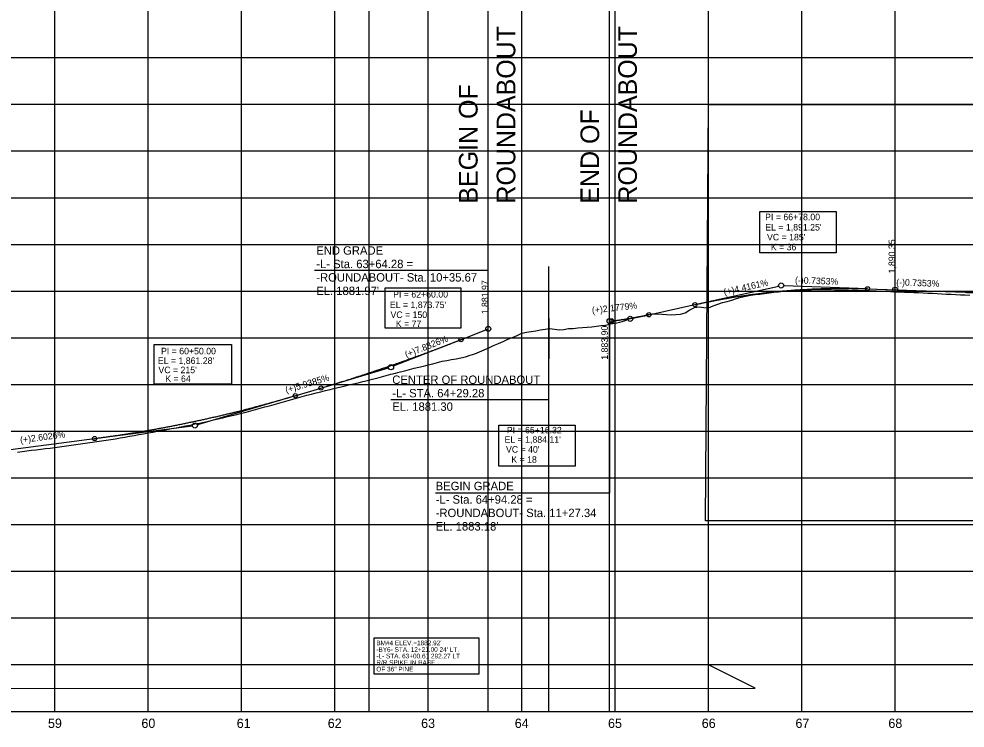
# Model space of a CAD drawing. Extents: x 553912 to 567693, y 512355 to 537539.
# Drawn here: x 562111 to 563124, y 513588 to 514347 of the extents above; entities that cross this region are included whole.
import ezdxf

# ---------------------------------------------------------------- set-up
doc = ezdxf.new("R2010")
doc.units = 0
for name, color, linetype in [('Exist DTM Spot Elevation Text', 7, 'Continuous'), ('Exist Profile Cell', 7, 'Continuous'), ('Exist Vertical Profile Ground Line', 7, 'Continuous'), ('Exist Vertical Profile Horizontal Axis Label Major', 7, 'Continuous'), ('Prop Vertical Profile Curve Label', 7, 'Continuous'), ('Prop Vertical Profile Grade', 7, 'Continuous'), ('Prop Vertical Profile Grade Label', 7, 'Continuous'), ('Prop VPI Label', 7, 'Continuous'), ('Scratch_Level_1', 7, 'Continuous'), ('Scratch_Level_5', 7, 'Continuous'), ('Sheet Profile Grid Major CELL', 7, 'Continuous')]:
    doc.layers.add(name, color=color, linetype=linetype)

msp = doc.modelspace()

# ---------------------------------------------------------------- linework, layer by layer
at = {"layer": 'Exist DTM Spot Elevation Text'}
msp.add_lwpolyline([(562491.3, 513645.9), (562603.8, 513645.9), (562603.8, 513683.9), (562491.3, 513683.9)], close=True, dxfattribs=at)
at = {"layer": 'Exist Profile Cell'}
msp.add_line((557249.5, 513605.4), (563849.5, 513605.4), dxfattribs=at)
msp.add_line((557249.5, 513605.4), (563849.5, 513605.4), dxfattribs=at)
at = {"layer": 'Exist Vertical Profile Ground Line'}
for points in [[(562749.5, 514021.5), (562754.5, 514022.4), (562759.5, 514024), (562764.5, 514026.1), (562769.5, 514027.4), (562774.5, 514028.4), (562779.5, 514029.4), (562784.5, 514030.5), (562789.5, 514031.5), (562794.5, 514031.2), (562799.5, 514030.9), (562804.5, 514030.6), (562809.5, 514030.4), (562814.5, 514030.6), (562819.5, 514030.9), (562824.5, 514032.3), (562829.5, 514035.7), (562834.5, 514038.2), (562839.5, 514039), (562844.5, 514038.3), (562849.5, 514037.9), (562854.5, 514040), (562859.5, 514041.8), (562864.5, 514043.4), (562869.5, 514044.7), (562874.5, 514046.1), (562879.5, 514047.8), (562884.5, 514049.3), (562889.5, 514050.3), (562894.5, 514051.2), (562899.5, 514051.9), (562904.5, 514052.6), (562909.5, 514053.3), (562914.5, 514053.9), (562919.5, 514054.5), (562924.5, 514055.1), (562929.5, 514055.7), (562934.5, 514056.2), (562939.5, 514056.4), (562944.5, 514056.6), (562949.5, 514056.8), (562954.5, 514057), (562959.5, 514057.2), (562964.5, 514057.4), (562969.5, 514057.5), (562974.5, 514057.4), (562979.5, 514057.3), (562984.5, 514057.2), (562989.5, 514057.1), (562994.5, 514057), (562999.5, 514056.9), (563004.5, 514056.8), (563009.5, 514056.6), (563014.5, 514056.4), (563019.5, 514056.3), (563024.5, 514056.1), (563029.5, 514055.9), (563034.5, 514055.7), (563039.5, 514055.5), (563044.5, 514055.3), (563049.5, 514055.1), (563054.5, 514054.9), (563059.5, 514054.7), (563064.5, 514054.5), (563069.5, 514054.3), (563074.5, 514054.1), (563079.5, 514053.9), (563084.5, 514053.6), (563089.5, 514053.4), (563094.5, 514053.1), (563099.5, 514052.9), (563104.5, 514052.6), (563109.5, 514052.3), (563114.5, 514052.1), (563119.5, 514051.8), (563124.5, 514051.6), (563129.5, 514051.3)], [(562749.5, 514021.5), (562754.5, 514022.4), (562759.5, 514024), (562764.5, 514026.1), (562769.5, 514027.4), (562774.5, 514028.4), (562779.5, 514029.4), (562784.5, 514030.5), (562789.5, 514031.5), (562794.5, 514031.2), (562799.5, 514030.9), (562804.5, 514030.6), (562809.5, 514030.4), (562814.5, 514030.6), (562819.5, 514030.9), (562824.5, 514032.3), (562829.5, 514035.7), (562834.5, 514038.2), (562839.5, 514039), (562844.5, 514038.3), (562849.5, 514037.9), (562854.5, 514040), (562859.5, 514041.8), (562864.5, 514043.4), (562869.5, 514044.7), (562874.5, 514046.1), (562879.5, 514047.8), (562884.5, 514049.3), (562889.5, 514050.3), (562894.5, 514051.2), (562899.5, 514051.9), (562904.5, 514052.6), (562909.5, 514053.3), (562914.5, 514053.9), (562919.5, 514054.5), (562924.5, 514055.1), (562929.5, 514055.7), (562934.5, 514056.2), (562939.5, 514056.4), (562944.5, 514056.6), (562949.5, 514056.8), (562954.5, 514057), (562959.5, 514057.2), (562964.5, 514057.4), (562969.5, 514057.5), (562974.5, 514057.4), (562979.5, 514057.3), (562984.5, 514057.2), (562989.5, 514057.1), (562994.5, 514057), (562999.5, 514056.9), (563004.5, 514056.8), (563009.5, 514056.6), (563014.5, 514056.4), (563019.5, 514056.3), (563024.5, 514056.1), (563029.5, 514055.9), (563034.5, 514055.7), (563039.5, 514055.5), (563044.5, 514055.3), (563049.5, 514055.1), (563054.5, 514054.9), (563059.5, 514054.7), (563064.5, 514054.5), (563069.5, 514054.3), (563074.5, 514054.1), (563079.5, 514053.9), (563084.5, 514053.6), (563089.5, 514053.4), (563094.5, 514053.1), (563099.5, 514052.9), (563104.5, 514052.6), (563109.5, 514052.3), (563114.5, 514052.1), (563119.5, 514051.8), (563124.5, 514051.6), (563129.5, 514051.3)], [(562249.5, 513903.9), (562254.5, 513904.8), (562259.5, 513905.7), (562264.5, 513906.6), (562269.5, 513907.6), (562274.5, 513908.5), (562279.5, 513909.4), (562284.5, 513910.4), (562289.5, 513911.3), (562294.5, 513912.3), (562299.5, 513913.4), (562304.5, 513914.4), (562309.5, 513915.5), (562314.5, 513916.6), (562319.5, 513917.8), (562324.5, 513919), (562329.5, 513920.1), (562334.5, 513921.3), (562339.5, 513922.5), (562344.5, 513923.7), (562349.5, 513925), (562354.5, 513926.2), (562359.5, 513927.6), (562364.5, 513928.9), (562369.5, 513930.3), (562374.5, 513931.6), (562379.5, 513933), (562384.5, 513934.4), (562389.5, 513935.8), (562394.5, 513937.2), (562399.5, 513938.6), (562404.5, 513940), (562409.5, 513941.4), (562414.5, 513942.8), (562419.5, 513944.1), (562424.5, 513945.5), (562429.5, 513946.8), (562434.5, 513948), (562439.5, 513949.2), (562444.5, 513950.4), (562449.5, 513951.6), (562454.5, 513952.8), (562459.5, 513953.9), (562464.5, 513955.2), (562469.5, 513956.4), (562474.5, 513957.6), (562479.5, 513958.9), (562484.5, 513960.1), (562489.5, 513961.3), (562494.5, 513962.6), (562499.5, 513963.9), (562504.5, 513965.2), (562509.5, 513966.6), (562514.5, 513967.9), (562519.5, 513969.2), (562524.5, 513970.5), (562529.5, 513971.8), (562534.5, 513973.1), (562539.5, 513974.3), (562544.5, 513975.5), (562549.5, 513976.7), (562554.5, 513978), (562559.5, 513979.2), (562564.5, 513980.5), (562569.5, 513981.5), (562574.5, 513982.4), (562579.5, 513983.3), (562584.5, 513984.1), (562589.5, 513985.2), (562594.5, 513987), (562599.5, 513988.6), (562604.5, 513990.7), (562609.5, 513992.8), (562614.5, 513995), (562619.5, 513997.3), (562624.5, 513999.6), (562629.5, 514001.9), (562634.5, 514004.1), (562639.5, 514006.2), (562644.5, 514008.3), (562649.5, 514010.6), (562654.5, 514011.8), (562659.5, 514012.4), (562664.5, 514013.3), (562669.5, 514014.2), (562674.5, 514015.1), (562679.5, 514015.8), (562684.5, 514015), (562689.5, 514014.4), (562694.5, 514014.5), (562699.5, 514015.7), (562704.5, 514015.8), (562709.5, 514016.2), (562714.5, 514016.7), (562719.5, 514017.1), (562724.5, 514017.6), (562729.5, 514018.2), (562734.5, 514018.8), (562739.5, 514019.2), (562744.5, 514020.5), (562749.5, 514021.5)], [(562249.5, 513903.9), (562254.5, 513904.8), (562259.5, 513905.7), (562264.5, 513906.6), (562269.5, 513907.6), (562274.5, 513908.5), (562279.5, 513909.4), (562284.5, 513910.4), (562289.5, 513911.3), (562294.5, 513912.3), (562299.5, 513913.4), (562304.5, 513914.4), (562309.5, 513915.5), (562314.5, 513916.6), (562319.5, 513917.8), (562324.5, 513919), (562329.5, 513920.1), (562334.5, 513921.3), (562339.5, 513922.5), (562344.5, 513923.7), (562349.5, 513925), (562354.5, 513926.2), (562359.5, 513927.6), (562364.5, 513928.9), (562369.5, 513930.3), (562374.5, 513931.6), (562379.5, 513933), (562384.5, 513934.4), (562389.5, 513935.8), (562394.5, 513937.2), (562399.5, 513938.6), (562404.5, 513940), (562409.5, 513941.4), (562414.5, 513942.8), (562419.5, 513944.1), (562424.5, 513945.5), (562429.5, 513946.8), (562434.5, 513948), (562439.5, 513949.2), (562444.5, 513950.4), (562449.5, 513951.6), (562454.5, 513952.8), (562459.5, 513953.9), (562464.5, 513955.2), (562469.5, 513956.4), (562474.5, 513957.6), (562479.5, 513958.9), (562484.5, 513960.1), (562489.5, 513961.3), (562494.5, 513962.6), (562499.5, 513963.9), (562504.5, 513965.2), (562509.5, 513966.6), (562514.5, 513967.9), (562519.5, 513969.2), (562524.5, 513970.5), (562529.5, 513971.8), (562534.5, 513973.1), (562539.5, 513974.3), (562544.5, 513975.5), (562549.5, 513976.7), (562554.5, 513978), (562559.5, 513979.2), (562564.5, 513980.5), (562569.5, 513981.5), (562574.5, 513982.4), (562579.5, 513983.3), (562584.5, 513984.1), (562589.5, 513985.2), (562594.5, 513987), (562599.5, 513988.6), (562604.5, 513990.7), (562609.5, 513992.8), (562614.5, 513995), (562619.5, 513997.3), (562624.5, 513999.6), (562629.5, 514001.9), (562634.5, 514004.1), (562639.5, 514006.2), (562644.5, 514008.3), (562649.5, 514010.6), (562654.5, 514011.8), (562659.5, 514012.4), (562664.5, 514013.3), (562669.5, 514014.2), (562674.5, 514015.1), (562679.5, 514015.8), (562684.5, 514015), (562689.5, 514014.4), (562694.5, 514014.5), (562699.5, 514015.7), (562704.5, 514015.8), (562709.5, 514016.2), (562714.5, 514016.7), (562719.5, 514017.1), (562724.5, 514017.6), (562729.5, 514018.2), (562734.5, 514018.8), (562739.5, 514019.2), (562744.5, 514020.5), (562749.5, 514021.5)], [(562109.5, 513883.4), (562114.5, 513884), (562119.5, 513884.6), (562124.5, 513885.2), (562129.5, 513885.8), (562134.5, 513886.4), (562139.5, 513887), (562144.5, 513887.6), (562149.5, 513888.3), (562154.5, 513888.9), (562159.5, 513889.6), (562164.5, 513890.3), (562169.5, 513891), (562174.5, 513891.7), (562179.5, 513892.4), (562184.5, 513893.1), (562189.5, 513893.9), (562194.5, 513894.6), (562199.5, 513895.3), (562204.5, 513896), (562209.5, 513896.8), (562214.5, 513897.6), (562219.5, 513898.4), (562224.5, 513899.3), (562229.5, 513900.2), (562234.5, 513901.1), (562239.5, 513902), (562244.5, 513902.9), (562249.5, 513903.9)], [(562109.5, 513883.4), (562114.5, 513884), (562119.5, 513884.6), (562124.5, 513885.2), (562129.5, 513885.8), (562134.5, 513886.4), (562139.5, 513887), (562144.5, 513887.6), (562149.5, 513888.3), (562154.5, 513888.9), (562159.5, 513889.6), (562164.5, 513890.3), (562169.5, 513891), (562174.5, 513891.7), (562179.5, 513892.4), (562184.5, 513893.1), (562189.5, 513893.9), (562194.5, 513894.6), (562199.5, 513895.3), (562204.5, 513896), (562209.5, 513896.8), (562214.5, 513897.6), (562219.5, 513898.4), (562224.5, 513899.3), (562229.5, 513900.2), (562234.5, 513901.1), (562239.5, 513902), (562244.5, 513902.9), (562249.5, 513903.9)]]:
    msp.add_lwpolyline(points, dxfattribs=at)
at = {"layer": 'Prop Vertical Profile Curve Label'}
for centre in [(563020, 514058.2), (562835, 514041.2), (562745.8, 514023.8), (562785.8, 514030.4), (562584.5, 514003.7), (562407, 513943.7), (562434.5, 513951.9), (562192, 513897.8)]:
    msp.add_circle(centre, 2.25, dxfattribs=at)
at = {"layer": 'Prop Vertical Profile Grade'}
for p, q in [((563020, 514058.2), (563124.5, 514054.4)), ((563020, 514058.2), (563049.5, 514057.2)), ((562785.8, 514030.4), (562835, 514041.2)), ((562743.7, 514023.6), (562745.8, 514023.8)), ((562584.5, 514003.7), (562613.7, 514015.3)), ((562407, 513943.7), (562434.5, 513951.9)), ((562049.5, 513879.3), (562192, 513897.8))]:
    msp.add_line(p, q, dxfattribs=at)
for points in [[(562835, 514041.2), (562838.7, 514042), (562842.4, 514042.8), (562846.1, 514043.6), (562849.8, 514044.3), (562853.5, 514045.1), (562857.2, 514045.8), (562860.9, 514046.5), (562864.6, 514047.2), (562868.3, 514047.8), (562872, 514048.4), (562875.7, 514049.1), (562879.4, 514049.7), (562883.1, 514050.2), (562886.8, 514050.8), (562890.5, 514051.3), (562894.2, 514051.9), (562897.9, 514052.4), (562901.6, 514052.8), (562905.3, 514053.3), (562909, 514053.8), (562912.7, 514054.2), (562916.4, 514054.6), (562920.1, 514055), (562923.8, 514055.3), (562927.5, 514055.7), (562931.2, 514056), (562934.9, 514056.3), (562938.6, 514056.6), (562942.3, 514056.9), (562946, 514057.2), (562949.7, 514057.4), (562953.4, 514057.6), (562957.1, 514057.8), (562960.8, 514058), (562964.5, 514058.1), (562968.2, 514058.3), (562971.9, 514058.4), (562975.6, 514058.5), (562979.3, 514058.6), (562983, 514058.7), (562986.7, 514058.7), (562990.4, 514058.7), (562994.1, 514058.7), (562997.8, 514058.7), (563001.5, 514058.7), (563005.2, 514058.6), (563008.9, 514058.6), (563012.6, 514058.5), (563016.3, 514058.4), (563020, 514058.2)], [(563124.5, 514054.4), (563127.5, 514054.3), (563130.5, 514054.2), (563133.5, 514054.1), (563136.5, 514053.9), (563139.5, 514053.8), (563142.5, 514053.7), (563145.5, 514053.6), (563148.5, 514053.4), (563151.5, 514053.3), (563154.5, 514053.2), (563157.5, 514053), (563160.5, 514052.9), (563163.5, 514052.8), (563166.5, 514052.6), (563169.5, 514052.5), (563172.5, 514052.3), (563175.5, 514052.2), (563178.5, 514052), (563181.5, 514051.9), (563184.5, 514051.7), (563187.5, 514051.5), (563190.5, 514051.4), (563193.5, 514051.2), (563196.5, 514051), (563199.5, 514050.9), (563202.5, 514050.7), (563205.5, 514050.5), (563208.5, 514050.3), (563211.5, 514050.2), (563214.5, 514050), (563217.5, 514049.8), (563220.5, 514049.6), (563223.5, 514049.4), (563226.5, 514049.2), (563229.5, 514049), (563232.5, 514048.8), (563235.5, 514048.6), (563238.5, 514048.4), (563241.5, 514048.2), (563244.5, 514048), (563247.5, 514047.8), (563250.5, 514047.6), (563253.5, 514047.3), (563256.5, 514047.1), (563259.5, 514046.9), (563262.5, 514046.7), (563265.5, 514046.5), (563268.5, 514046.2), (563271.5, 514046), (563274.5, 514045.8)], [(562745.8, 514023.8), (562746.6, 514023.9), (562747.4, 514024), (562748.2, 514024), (562749, 514024.1), (562749.8, 514024.2), (562750.6, 514024.3), (562751.4, 514024.4), (562752.2, 514024.5), (562753, 514024.6), (562753.8, 514024.7), (562754.6, 514024.8), (562755.4, 514024.9), (562756.2, 514025.1), (562757, 514025.2), (562757.8, 514025.3), (562758.6, 514025.4), (562759.4, 514025.5), (562760.2, 514025.6), (562761, 514025.8), (562761.8, 514025.9), (562762.6, 514026), (562763.4, 514026.1), (562764.2, 514026.2), (562765, 514026.4), (562765.8, 514026.5), (562766.6, 514026.6), (562767.4, 514026.8), (562768.2, 514026.9), (562769, 514027.1), (562769.8, 514027.2), (562770.6, 514027.3), (562771.4, 514027.5), (562772.2, 514027.6), (562773, 514027.8), (562773.8, 514027.9), (562774.6, 514028.1), (562775.4, 514028.2), (562776.2, 514028.4), (562777, 514028.5), (562777.8, 514028.7), (562778.6, 514028.8), (562779.4, 514029), (562780.2, 514029.2), (562781, 514029.3), (562781.8, 514029.5), (562782.6, 514029.7), (562783.4, 514029.8), (562784.2, 514030), (562785, 514030.2), (562785.8, 514030.4)], [(562434.5, 513951.9), (562437.5, 513952.8), (562440.5, 513953.7), (562443.5, 513954.6), (562446.5, 513955.5), (562449.5, 513956.4), (562452.5, 513957.3), (562455.5, 513958.3), (562458.5, 513959.2), (562461.5, 513960.1), (562464.5, 513961.1), (562467.5, 513962), (562470.5, 513963), (562473.5, 513964), (562476.5, 513964.9), (562479.5, 513965.9), (562482.5, 513966.9), (562485.5, 513967.9), (562488.5, 513968.9), (562491.5, 513969.9), (562494.5, 513970.9), (562497.5, 513971.9), (562500.5, 513972.9), (562503.5, 513973.9), (562506.5, 513974.9), (562509.5, 513976), (562512.5, 513977), (562515.5, 513978.1), (562518.5, 513979.1), (562521.5, 513980.2), (562524.5, 513981.2), (562527.5, 513982.3), (562530.5, 513983.4), (562533.5, 513984.5), (562536.5, 513985.5), (562539.5, 513986.6), (562542.5, 513987.7), (562545.5, 513988.8), (562548.5, 513989.9), (562551.5, 513991.1), (562554.5, 513992.2), (562557.5, 513993.3), (562560.5, 513994.4), (562563.5, 513995.6), (562566.5, 513996.7), (562569.5, 513997.9), (562572.5, 513999), (562575.5, 514000.2), (562578.5, 514001.4), (562581.5, 514002.5), (562584.5, 514003.7)], [(562192, 513897.8), (562196.3, 513898.4), (562200.6, 513899), (562204.9, 513899.6), (562209.2, 513900.2), (562213.5, 513900.8), (562217.8, 513901.4), (562222.1, 513902.1), (562226.4, 513902.7), (562230.7, 513903.4), (562235, 513904.1), (562239.3, 513904.8), (562243.6, 513905.6), (562247.9, 513906.3), (562252.2, 513907), (562256.5, 513907.8), (562260.8, 513908.6), (562265.1, 513909.4), (562269.4, 513910.2), (562273.7, 513911), (562278, 513911.9), (562282.3, 513912.7), (562286.6, 513913.6), (562290.9, 513914.5), (562295.2, 513915.4), (562299.5, 513916.3), (562303.8, 513917.2), (562308.1, 513918.1), (562312.4, 513919.1), (562316.7, 513920.1), (562321, 513921), (562325.3, 513922), (562329.6, 513923.1), (562333.9, 513924.1), (562338.2, 513925.1), (562342.5, 513926.2), (562346.8, 513927.2), (562351.1, 513928.3), (562355.4, 513929.4), (562359.7, 513930.5), (562364, 513931.7), (562368.3, 513932.8), (562372.6, 513934), (562376.9, 513935.1), (562381.2, 513936.3), (562385.5, 513937.5), (562389.8, 513938.7), (562394.1, 513939.9), (562398.4, 513941.2), (562402.7, 513942.4), (562407, 513943.7)]]:
    msp.add_spline(points, degree=3, dxfattribs=at)
at = {"layer": 'Prop VPI Label'}
for p, q in [((562613.7, 514077.6), (562427.7, 514077.6)), ((562613.7, 514013.4), (562613.7, 514077.6)), ((562835, 514041.2), (562924.8, 514061.1)), ((563020, 514058.2), (562930.2, 514061.5)), ((562678.7, 514026.4), (562678.1, 513939.3)), ((562745.8, 514023.8), (562763, 514025.7)), ((562785.8, 514030.4), (562768.5, 514026.5)), ((562743.7, 514024.9), (562743.7, 513839.2)), ((562584.5, 514003.7), (562512, 513975.2)), ((562434.5, 513951.9), (562506.8, 513973.4)), ((562407, 513943.7), (562302.1, 513912.6)), ((562407, 513943.7), (562302.1, 513912.6)), ((562678.1, 513939.3), (562509.4, 513939.3)), ((562192, 513897.8), (562296.7, 513911.4)), ((562743.7, 513839.2), (562557.1, 513839.2))]:
    msp.add_line(p, q, dxfattribs=at)
for points in [[(562904.6, 514140.9), (562986.5, 514140.9), (562986.5, 514096.8), (562904.6, 514096.8)], [(562503.4, 514059.2), (562584.5, 514059.2), (562584.5, 514016), (562503.4, 514016)], [(562255.9, 513998.7), (562338.7, 513998.7), (562338.7, 513956), (562255.9, 513956)], [(562624.9, 513912.3), (562706.8, 513912.3), (562706.8, 513868.3), (562624.9, 513868.3)]]:
    msp.add_lwpolyline(points, close=True, dxfattribs=at)
for centre in [(562927.5, 514061.7), (563049.5, 514057.2), (562743.7, 514023.6), (562765.8, 514026), (562613.7, 514015.3), (562509.5, 513974.2), (562299.5, 513911.8)]:
    msp.add_circle(centre, 2.75, dxfattribs=at)
at = {"layer": 'Scratch_Level_1'}
for p, q in [((562486.3, 513605.4), (562486.3, 515429.3)), ((562949.5, 513605.4), (562949.5, 515429.3))]:
    msp.add_line(p, q, dxfattribs=at)
at = {"layer": 'Scratch_Level_5'}
for p, q in [((562613.7, 513605.4), (562613.7, 514805.4)), ((562743.7, 513605.4), (562743.7, 514805.4)), ((562678.7, 513605.4), (562678.7, 514081.9))]:
    msp.add_line(p, q, dxfattribs=at)
for points in [[(562849.5, 514255.4), (563578.6, 514255.4), (563575.5, 513809.8), (562846.4, 513809.8)], [(561449.5, 514155.4), (561449.5, 513655.4), (561439, 513643.8), (561437, 513630.4), (562847.9, 513630.3), (562899.5, 513630.4), (562849.5, 513655.4), (562849.5, 514155.4)]]:
    msp.add_lwpolyline(points, close=True, dxfattribs=at)
at = {"layer": 'Sheet Profile Grid Major CELL'}
for p, q in [((562149.5, 513605.4), (562149.5, 514805.4)), ((562249.5, 513605.4), (562249.5, 514805.4)), ((562349.5, 513605.4), (562349.5, 514805.4)), ((562449.5, 513605.4), (562449.5, 514805.4)), ((562549.5, 513605.4), (562549.5, 514805.4)), ((562649.5, 513605.4), (562649.5, 514805.4)), ((562749.5, 513605.4), (562749.5, 514805.4)), ((562849.5, 513605.4), (562849.5, 514805.4)), ((562949.5, 513605.4), (562949.5, 514805.4)), ((563049.5, 513605.4), (563049.5, 514805.4)), ((563849.5, 514305.4), (557249.5, 514305.4)), ((563849.5, 514255.4), (557249.5, 514255.4)), ((563849.5, 514205.4), (557249.5, 514205.4)), ((563849.5, 514155.4), (557249.5, 514155.4)), ((563849.5, 514105.4), (557249.5, 514105.4)), ((563849.5, 514055.4), (557249.5, 514055.4)), ((563849.5, 514005.4), (557249.5, 514005.4)), ((563849.5, 513955.4), (557249.5, 513955.4)), ((563849.5, 513905.4), (557249.5, 513905.4)), ((563849.5, 513855.4), (557249.5, 513855.4)), ((563849.5, 513805.4), (557249.5, 513805.4)), ((563849.5, 513755.4), (557249.5, 513755.4)), ((563849.5, 513705.4), (557249.5, 513705.4)), ((563849.5, 513655.4), (557249.5, 513655.4))]:
    msp.add_line(p, q, dxfattribs=at)

# ---------------------------------------------------------------- texts
at = {"layer": 'Exist DTM Spot Elevation Text'}
for s, p in [("BM#4 ELEV.=1882.92'", (562493.8, 513676.4)), ("-BY6- STA. 12+21.00 24' LT.", (562493.8, 513669.4)), ('-L- STA. 63+00.61 292.27 LT', (562493.8, 513662.4)), ('OF 36" PINE', (562493.8, 513648.4)), ('R/R SPIKE IN BASE', (562493.8, 513655.4))]:
    msp.add_text(s, height=5, dxfattribs=at).set_placement(p)
at = {"layer": 'Exist Vertical Profile Horizontal Axis Label Major'}
for s, p in [('59', (562142.1, 513587.9)), ('59', (562142.1, 513587.9)), ('60', (562242.2, 513587.9)), ('60', (562242.2, 513587.9)), ('61', (562344.3, 513587.9)), ('61', (562344.3, 513587.9)), ('62', (562441.8, 513587.9)), ('62', (562441.8, 513587.9)), ('63', (562541.8, 513587.9)), ('63', (562541.8, 513587.9)), ('64', (562642.1, 513587.9)), ('64', (562642.1, 513587.9)), ('65', (562742, 513587.9)), ('65', (562742, 513587.9)), ('66', (562842.4, 513587.9)), ('66', (562842.4, 513587.9)), ('67', (562942.8, 513587.9)), ('67', (562942.8, 513587.9)), ('68', (563042.3, 513587.9)), ('68', (563042.3, 513587.9))]:
    msp.add_text(s, height=10, dxfattribs=at).set_placement(p)
at = {"layer": 'Prop Vertical Profile Curve Label'}
for s, p in [("VC = 185'", (562912.3, 514110)), ('K = 36', (562916.4, 514099.4)), ("VC = 150'", (562509, 514026.9)), ('K = 77', (562514.7, 514017.2)), ("VC = 215'", (562260.4, 513967.8)), ('K = 64', (562267.7, 513958.4)), ("VC = 40'", (562632.7, 513882.7)), ('K = 18', (562638.4, 513871.9))]:
    msp.add_text(s, height=7, dxfattribs=at).set_placement(p)
at = {"layer": 'Prop Vertical Profile Grade Label'}
for s, rotation, p in [('(+)4.4161%', 12.4515, (562866.7, 514051.3)), ('(-)0.7353%', 357.8945, (562942.2, 514064.1)), ('(-)0.7353%', 357.8945, (563050.6, 514061.9)), ('(+)2.1779%', 6.2146, (562725.1, 514031.7)), ('(+)7.8826%', 21.5109, (562526, 513984.2)), ('(+)5.9385%', 16.5375, (562397.4, 513946.3)), ('(+)2.6026%', 7.4143, (562112.7, 513892.8))]:
    msp.add_text(s, height=7, rotation=rotation, dxfattribs=at).set_placement(p)
at = {"layer": 'Prop VPI Label'}
for s, height, p in [('PI = 66+78.00', 7, (562910.3, 514131.6)), ("EL = 1,891.25'", 7, (562910.4, 514120.6)), ('END GRADE ', 9, (562429.5, 514094.7)), ('-L- Sta. 63+64.28 =', 9, (562429.5, 514080.3)), ('-ROUNDABOUT- Sta. 10+35.67', 9, (562429.5, 514065.9)), ("EL. 1881.97'", 9, (562429.5, 514051.5)), ('PI = 62+60.00', 7, (562511.8, 514048.8)), ("EL = 1,873.75'", 7, (562508.3, 514037.5)), ('PI = 60+50.00', 7, (562263.2, 513988)), ("EL = 1,861.28'", 7, (562259.8, 513977.7)), ('CENTER OF ROUNDABOUT', 9, (562510.9, 513956.3)), ('-L- STA. 64+29.28', 9, (562510.9, 513941.9)), ('EL. 1881.30', 9, (562510.9, 513927.5)), ('PI = 65+16.32', 7, (562633.6, 513903.3)), ("EL = 1,884.11'", 7, (562631.1, 513893.3)), ('BEGIN GRADE ', 9, (562557.4, 513842.5)), ('-L- Sta. 64+94.28 =', 9, (562557.4, 513828.1)), ('-ROUNDABOUT- Sta. 11+27.34', 9, (562557.4, 513813.7)), ("EL. 1883.18'", 9, (562557.4, 513799.3))]:
    msp.add_text(s, height=height, dxfattribs=at).set_placement(p)
for s, p in [('1,890.35', (563049.5, 514074.7)), ('1,881.97', (562613.7, 514030.9)), ('1,883.90', (562741.8, 513982.2))]:
    msp.add_text(s, height=7, rotation=90, dxfattribs=at).set_placement(p)
at = {"layer": 'Scratch_Level_5'}
for s, p in [('ROUNDABOUT', (562642.7, 514149.4)), ('ROUNDABOUT', (562772.9, 514149.4)), ('BEGIN OF ', (562602.3, 514149.4)), ('END OF ', (562732.5, 514149.4))]:
    msp.add_text(s, height=20, rotation=90, dxfattribs=at).set_placement(p)

doc.saveas('drawing.dxf')
